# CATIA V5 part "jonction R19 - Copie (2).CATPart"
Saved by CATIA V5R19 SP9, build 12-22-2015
Part number: Part1
Bounding box of the stored display mesh (mm): x -13.996 to 13.996, y 0 to 30, z -13.996 to 120
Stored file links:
  C:\Users\hbezard\Documents\Perso\imprimante 3d\pieces\rincepot\jonction R19.CATPart
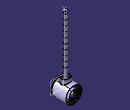
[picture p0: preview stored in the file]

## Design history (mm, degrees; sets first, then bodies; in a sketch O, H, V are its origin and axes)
Parameters
  `dia admi` = 22
  `dia evac` = 10
  `paroies hp` = 2
  `paroies bp` = 2
  `longueur filetee` = 5
  `pas jonction` = 2
  `prof filet jonction` = 1
  `dia gourde` = 12
  `pas gourde` = 2
  `entree gourde` = 8
  `longueur jonction` = 30
  `dia injection` = 8
  `longueur injection` = 110
  `longueur gourde` = 30
  `dia inter injection` = 6
  Real = 0
Body1 (main body)
  Sketch1 on yz-plane, origin (0, 0, 0), H (0, 1, 0), V (0, 0, 1)
    line L1 (0, 5) -> (0, 6)
    line L2 (0, 6) -> (5.5, 6)
    line L3 (5.5, 6) -> (5.5, 8)
    line L4 (5.5, 8) -> (30, 8)
    line L5 (30, 8) -> (30, 7)
    line L6 (30, 7) -> (24.5, 7)
    line L7 (24.5, 7) -> (24.5, 5)
    line L8 (24.5, 5) -> (0, 5)
    reference intersected line E1 through (0, 0) direction (0, 1) from zx-plane
    axis line L9 (-32.3822, 0) -> (183.7177, 0)
    line L10 (0, 11) -> (0, 12)
    line L11 (0, 12) -> (5.5, 12)
    line L12 (5.5, 14) -> (30, 14)
    line L13 (30, 14) -> (30, 13)
    line L14 (30, 13) -> (24.5, 13)
    line L15 (24.5, 11) -> (0, 11)
    line L16 (5.5, 12) -> (5.5, 14)
    line L17 (24.5, 13) -> (24.5, 11)
    point P19 (-31.9622, 57.8884)
    reference intersected line E2 through (0, 0) direction (-1, 0) from xy-plane
    distance L2 L8 = 1
    distance L8 L9 = 5
    angle L2 L3 = 90
    length L2 = 5.5
    distance L1 L5 = 30
    length L6 = 5.5 {= Sketch1.length(L2)}
    distance L4 L6 = 1 {= Sketch1.distance(L2 L8)}
    distance L11 L15 = 1
    angle L11 L16 = 90
    length L11 = 5.5
    distance L10 L13 = 30
    length L14 = 5.5 {= Sketch1.length(L11)}
    distance L12 L14 = 1 {= Sketch1.distance(L11 L15)}
    distance L15 L9 = 11
    distance L14 L11 = 1
    distance L6 L2 = 1
    vertical: L1 V, L5 V, L10 V, L13 V
    horizontal: L2 H, L4 H, L6 H, L8 H, L9 H, L11 H, L12 H, L14 H, L15 H
    coincidence: L1 E1, L10 E1, L9 E2
    parallelism: L7 L3, L17 L16
  Shaft1 "jonction": profile Sketch1, axis Sketch1.L9, angle 360
  Plane1: type Offset, RefPlane xy-plane, Offset 20
  Sketch2 on Plane1, origin (0, 0, 20), H (1, 0, 0), V (0, 1, 0)
    circle A1 centre (0, 15) radius 7.5
    point P1 (0, 15)
    reference intersected line E1 through (0, 0) direction (0, 1) from yz-plane
    reference intersected line E2 through (0, 0) direction (-1, 0) from zx-plane
    distance P1 E2 = 15
    radius A1 = 7.5
    coincidence: P1 E1
  Pad1 "gourde": profile Sketch2, direction (0, 0, -1), up to face of Shaft1 from Sketch1.L12
  Sketch3 on Plane1, origin (0, 0, 20), H (1, 0, 0), V (0, 1, 0)
    point P1 (0, 15)
    reference intersected line E1 through (0, 0) direction (0, 1) from yz-plane
    reference intersected line E2 through (0, 0) direction (-1, 0) from zx-plane
    circle A1 centre (0, 15) radius 3
    distance P1 E2 = 15
    radius A1 = 3
    coincidence: P1 E1
  Pocket1: profile a sketch, direction (0, 0, -1), up to face of Shaft1 from Sketch1.L15
  Pad2: profile Sketch3, direction (0, 0, -1), up to face of Shaft1 from Sketch1.L4, opposite side length 100
  Sketch4 on Plane1, origin (0, 0, 20), H (1, 0, 0), V (0, 1, 0)
    circle A1 centre (0, 15) radius 2
    reference projected point E1 (0, 15) from axis of face of Pad2 from Sketch3.A1
    reference projected circle E2 centre (0, 15) radius 3 from Sketch3.A1
    distance A1 E2 = 1
    concentricity: A1 E1
  Pocket2: profile Sketch4, direction (0, 0, -1), through (limit type 6), opposite side length 98
  Plane2: type Angle, RefPlane yz-plane, Direction Y axis, Angle -30
  Plane3: type Offset, RefPlane {inverselocal InverseElem Plane2}, Offset 10, reversed
  Sketch5 on Plane3, origin (-4.0798, 0, 27.0665), H (0, -1, 0), V (-0.5, 0, 0.866)
    line L1 (-6, -23.9802) -> (-7.3377, -23.9802)
    line L2 (-7.3377, -23.9802) -> (-7.3377, -26.9802)
    line L3 (-7.3377, -26.9802) -> (-6, -26.9802)
    line L4 (-6, -26.9802) -> (-6, -23.9802)
    point P5 (-24, -23.9802)
    line L5 (-24, -23.9802) -> (-22.6623, -23.9802)
    line L6 (-22.6623, -23.9802) -> (-22.6623, -26.9802)
    line L7 (-22.6623, -26.9802) -> (-24, -26.9802)
    line L8 (-24, -26.9802) -> (-24, -23.9802)
    point P7 (-22.6623, -26.9802)
    reference intersected line E1 through (0, 0) direction (0, -1) from face of Shaft1 from Sketch1.L10
    reference intersected line E2 through (-30, 0) direction (0, -1) from face of Shaft1 from Sketch1.L13
    reference projected line E3 through (0, -25.4802) direction (-1, 0) from axis of face of Shaft1 from Sketch1.L8
    length L3 = 1.3377
    length L7 = 1.3377 {= Sketch5.length(L3)}
    distance L3 L1 = 3
    distance L4 E1 = 6
    distance L8 E2 = 6
    horizontal: L1 H, L3 H, L5 H, L7 H
    vertical: L2 V, L4 V, L6 V, L8 V
    coincidence: P5 L1, P7 L3
    symmetry: L3 L1 E3
  Pad3: profile Sketch5, direction (-0.866, 0, -0.5), up to face of Shaft1 from Sketch1.L4, opposite side up to face of Shaft1 from Sketch1.L15
  Mirror1: of Pad3, about yz-plane
  Plane4: type Offset, RefPlane xy-plane, Offset 10, reversed
  Sketch6 on Plane4, origin (0, 0, -10), H (1, 0, 0), V (0, 1, 0)
    point P1 (0, 8)
    line L1 (1, 10) -> (1, 6)
    line L2 (1, 6) -> (-1, 6)
    line L3 (-1, 6) -> (-1, 10)
    line L4 (-1, 10) -> (1, 10)
    point P6 (0, 22)
    line L5 (1, 24) -> (1, 20)
    line L6 (1, 20) -> (-1, 20)
    line L7 (-1, 20) -> (-1, 24)
    line L8 (-1, 24) -> (1, 24)
    point P8 (1, 20)
    reference projected line E1 through (0, 0) direction (0, 1) from axis of face of Shaft1 from Sketch1.L8
    reference intersected line E2 through (0, 0) direction (-1, 0) from face of Shaft1 from Sketch1.L10
    reference projected line E3 (-13, 30) -> (13, 30) from edge [face of Shaft1 from Sketch1.L12 | face of Shaft1 from Sketch1.L13]
    length L3 = 4
    length L7 = 4 {= Sketch6.length(L3)}
    length L4 = 2
    distance L2 E2 = 6
    distance L8 E3 = 6
    vertical: L1 V, L3 V, L5 V, L7 V
    horizontal: L2 H, L4 H, L6 H, L8 H
    equidistance: L1 L3 P1, L2 L4 P1, L5 L7 P6, L6 L8 P6
    coincidence: P8 L1, P1 E1, L7 L3
  Pad4: profile Sketch6, direction (0, 0, 1), up to face of Shaft1 from Sketch1.L4, opposite side up to face of Shaft1 from Sketch1.L15
  Fillet1: radius 0.5, on face of Pad4 from Sketch6.L2; face of Pad4 from Sketch6.L1; face of Pad4 from Sketch6.L3; face of Pad4 from Sketch6.L4; face of Pad4 from Sketch6.L8; face of Pad4 from Sketch6.L5; face of Pad4 from Sketch6.L6; face of Pad4 from Sketch6.L7
  Fillet2: radius 0.5, on face of Pad3 from Sketch5.L8; face of Pad3 from Sketch5.L7; face of Pad3 from Sketch5.L5; face of Pad3 from Sketch5.L6; face of Pad3 from Sketch5.L4; face of Pad3 from Sketch5.L3; face of Pad3 from Sketch5.L1; face of Pad3 from Sketch5.L2; face of Mirror1 (x8)
  Fillet3: radius 0.5, on edge [face of Shaft1 from Sketch1.L4 | face of Pad2 from Sketch3.A1]
  Fillet4: radius 0.5, on edge [face of Pad1 from Sketch2.A1 | face of Shaft1 from Sketch1.L12]
  Point1: type Center, Curve edge [face of Shaft1 from Sketch1.L13 | face of Shaft1 from Sketch1.L14]
  Helix1: Direction Y axis, RefPoint {point type Coord, X 0, Y -1.155, Z 0, RefPoint vertex [element of Sketch1 | element of Sketch1]}, Pitch 2, Height 3.5, TaperAngle 0
  Sketch7 on yz-plane, origin (0, 0, 0), H (0, 1, 0), V (0, 0, 1)
    point P1 (3.7679, 12)
    line L1 (3.7679, 12) -> (4.9226, 12)
    point P2 (4.9226, 12)
    line L2 (4.9226, 12) -> (4.3453, 13)
    point P3 (4.3453, 13)
    line L3 (4.3453, 13) -> (3.7679, 12)
    axis line L4 (4.3453, 15.5745) -> (4.3453, 9.1301)
    reference projected line E1 (5.5, 12) -> (0, 12) from Sketch1.L11
    reference projected line E2 (5.5, 14) -> (5.5, -14) from edge [face of Shaft1 from Sketch1.L16 | face of Shaft1 from Sketch1.L12]
    length L4 = 6.4444
    angle L2 L1 = 60
    distance L1 P3 = 1
    distance L1 E1 = 0
    distance L4 E2 = 1.1547 {= Sketch7.length(L1)}
    length L1 = 1.1547 (reference)
    horizontal: L1 H
    vertical: L4 V
    symmetry: P2 P1 L4
    coincidence: P3 L4
  Rib1: profile Sketch7, centre curve Helix1
  Fillet5: radius 0.5, on face of Rib1, deactivated
  Fillet6: radius 0.5, on face of Rib1
  Helix2: Direction Y axis, RefPoint vertex [element of Sketch1 | element of Sketch1], Pitch 2, Height 4, TaperAngle 0
  Sketch8 on yz-plane, origin (0, 0, 0), H (0, 1, 0), V (0, 0, 1)
    point P1 (0, 6)
    line L1 (0, 6) -> (1.1547, 6)
    point P2 (1.1547, 6)
    line L2 (1.1547, 6) -> (0.5774, 7)
    point P3 (0.5774, 7)
    line L3 (0.5774, 7) -> (0, 6)
    axis line L4 (0.5774, 18.6338) -> (0.5774, 12.1894)
    reference projected point E1 (0, 6) from vertex [element of Sketch1 | element of Sketch1]
    length L4 = 6.4444
    angle L2 L1 = 60
    distance L1 P3 = 1
    horizontal: L1 H
    vertical: L4 V
    symmetry: P2 P1 L4
    coincidence: P3 L4, P1 E1
  Rib2: profile Sketch8, centre curve Helix2
  Fillet7: radius 0.5, on face of Rib2
  Fillet8: radius 0.5, on face of Rib2
  Sketch9 on yz-plane, origin (0, 0, 0), H (0, 1, 0), V (0, 0, 1)
    point P1 (30, 13)
    line L1 (30, 13) -> (28.8453, 13)
    point P2 (28.8453, 13)
    line L2 (28.8453, 13) -> (29.4226, 12)
    point P3 (29.4226, 12)
    line L3 (29.4226, 12) -> (30, 13)
    axis line L4 (29.4226, 19.8788) -> (29.4226, 13.4344)
    reference projected point E1 (30, 13) from vertex [element of Sketch1 | element of Sketch1]
    length L4 = 6.4444
    angle L2 L1 = 60
    distance L1 P3 = 1
    horizontal: L1 H
    vertical: L4 V
    symmetry: P2 P1 L4
    coincidence: P3 L4, P1 E1
  Sketch10 on yz-plane, origin (0, 0, 0), H (0, 1, 0), V (0, 0, 1)
    point P1 (30, 7)
    line L1 (30, 7) -> (28.8453, 7)
    point P2 (28.8453, 7)
    line L2 (28.8453, 7) -> (29.4226, 6)
    point P3 (29.4226, 6)
    line L3 (29.4226, 6) -> (30, 7)
    axis line L4 (29.4226, 13.8788) -> (29.4226, 7.4344)
    reference projected point E1 (30, 7) from vertex [element of Sketch1 | element of Sketch1]
    length L4 = 6.4444
    angle L2 L1 = 60
    distance L1 P3 = 1
    horizontal: L1 H
    vertical: L4 V
    symmetry: P2 P1 L4
    coincidence: P3 L4, P1 E1
  Helix3: Direction Y axis, RefPoint vertex [element of Sketch1 | element of Sketch1], Pitch 2, Height 4, TaperAngle 0
  Helix4: Direction Y axis, RefPoint vertex [element of Sketch1 | element of Sketch1], Pitch 2, Height 4, TaperAngle 0
  Rib3: profile Sketch9, centre curve Helix3
  Rib4: profile Sketch10, centre curve Helix4
  Fillet9: radius 0.5, on face of Rib3
  Fillet10: radius 0.5, on face of Rib4
  Fillet11: radius 0.5, on face of Rib4
  Fillet12: radius 0.5, on face of Rib3
  Sketch11 on start face of Pad2, origin (0, 15, 120), H (1, 0, 0), V (0, 1, 0)
    point P1 (0, 0)
  Hole1: placed by Sketch11, at (0, 15, 120) direction (0, 0, -1), diameter 1, through (limit type 6)
  Point2: type OnCurve, Support edge [face of Pad2 from Sketch3.A1 | start face of Pad2], RefPoint {extremum Reference edge [face of Pad2 from Sketch3.A1 | start face of Pad2], Direction (1, 2, 3)}, Ratio 0.5
  Helix5: Direction {line type PtDir, RefPoint {point type Center, Curve edge [face of Pad2 from Sketch3.A1 | start face of Pad2]}, Direction start face of Pad2, Start 0, End 20}, RefPoint {point type OnCurve, Support a sketch, RefPoint {extremum Reference a sketch, Direction (1, 2, 3)}, Ratio 0.5}, Pitch 2, Height 5, TaperAngle 0
  Sketch12 on yz-plane, origin (0, -0.7113, -0.4445), H (0, 1, 0), V (0, 0, 1)
    point P1 (15.7113, 116.4445)
    reference projected line E1 through (15.7113, 0) direction (0, 1) from axis of face of Pad2 from Sketch3.A1
    reference intersected line E2 (12.7113, 120.4445) -> (18.7113, 120.4445) from start face of Pad2
    distance P1 E2 = 4
    coincidence: P1 E1
  Hole2: placed by Sketch12, at (0, 15, 116) direction (-1, 0, 0), diameter 1, through (limit type 3)
  CircPattern1: of Hole2, instances 8, angular step 45, axis from {line type PtDir, RefPoint {point type Center, Curve edge [face of Pad2 from Sketch3.A1 | start face of Pad2]}, Direction start face of Pad2, Start 0, End 20}
  RectPattern1: of CircPattern1, direction 1 instances 10, spacing 9, along Z axis reversed
  Plane5: type Normal, Curve edge [start face of Pad1 | face of Pocket1], RefPoint vertex of Helix5
  Sketch13 on Plane5, origin (-6.7082, 1.5836, 0), H (0.4472, 0.8944, 0), V (0, 0, 1)
    point P1 (8.5, 20)
    line L1 (8.5, 20) -> (8.5, 18.8453)
    point P2 (8.5, 18.8453)
    line L2 (8.5, 18.8453) -> (9.5, 19.4226)
    point P3 (9.5, 19.4226)
    line L3 (9.5, 19.4226) -> (8.5, 20)
    axis line L4 (6.1394, 19.4226) -> (12.5838, 19.4226)
    point P4 (6.1394, 19.4226)
    reference projected point E1 (8.5, 20) from vertex of Helix5
    length L4 = 6.4444
    angle L2 L1 = 60
    distance L1 P3 = 1
    distance L1 P4 = 2.3606
    symmetry: P2 P1 L4
    coincidence: P3 L4, P1 E1
    perpendicularity: L4 L1
    vertical: L1 V
  Rib5: profile Sketch13, centre curve Helix5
